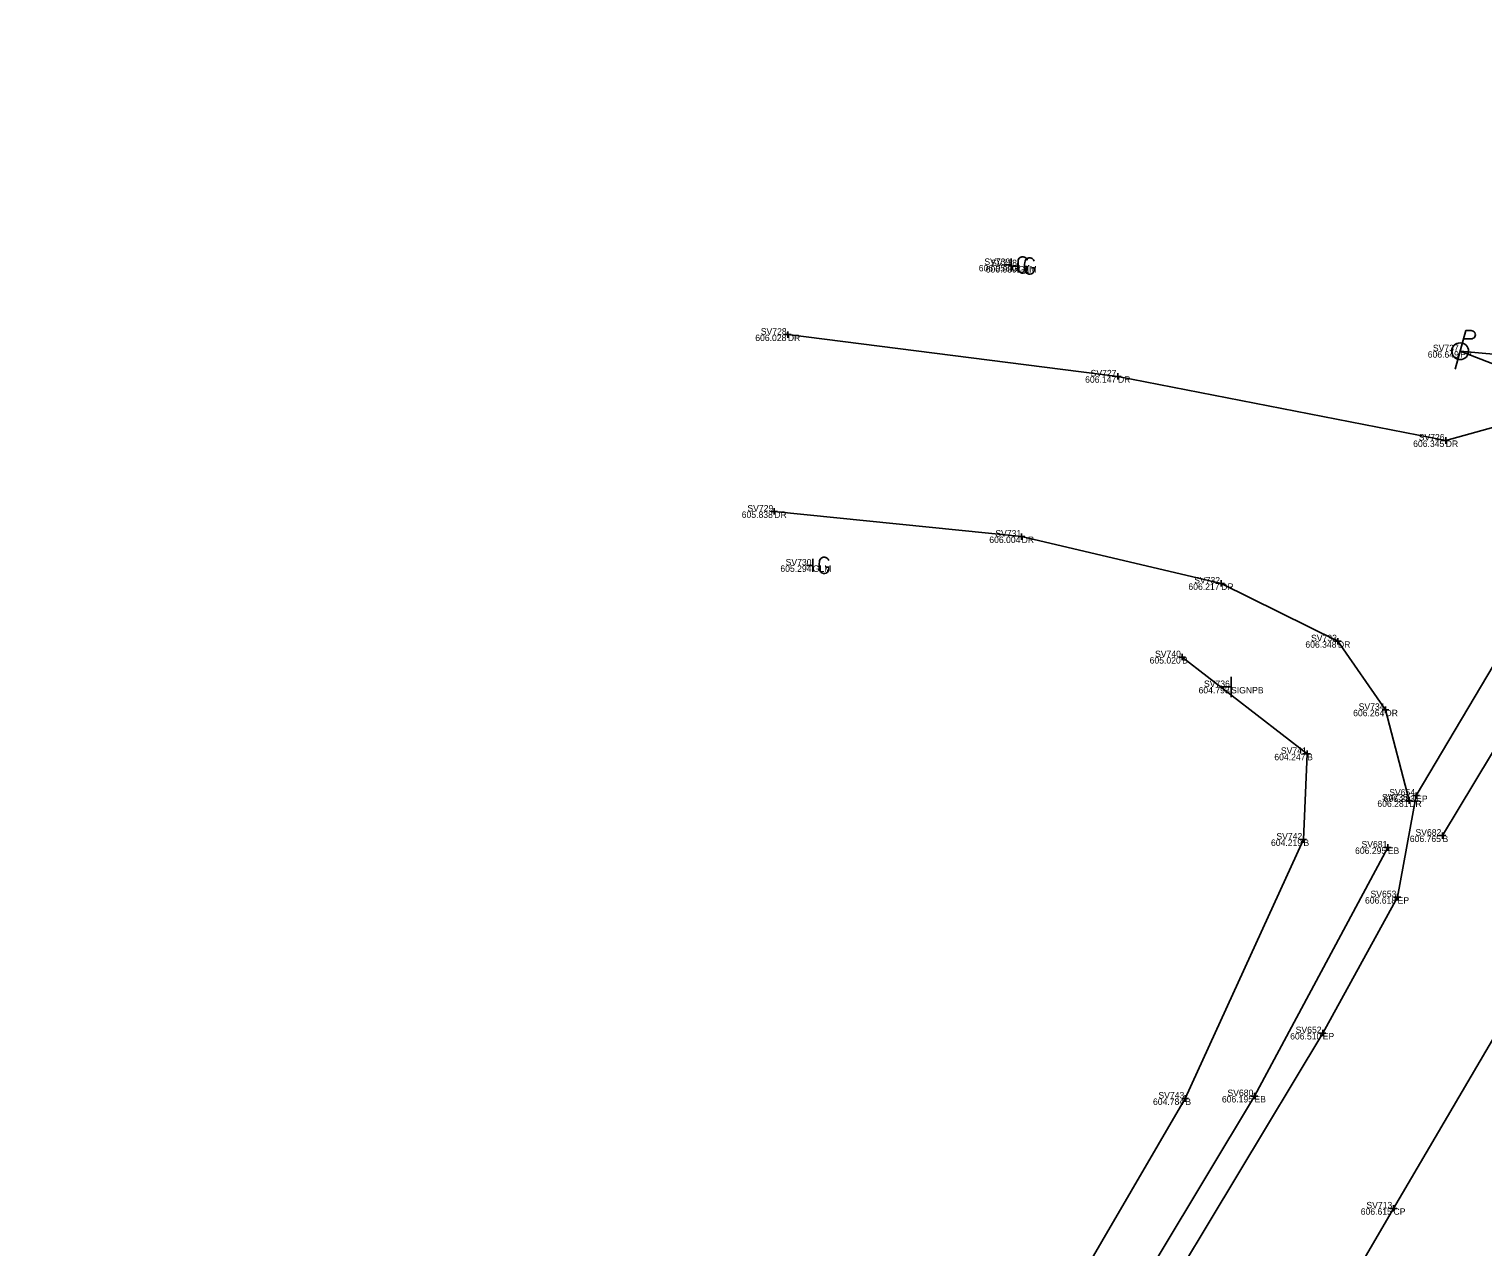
# Model space of a CAD drawing. Extents: x -2 to 1979875, y -2 to 232027.
# Drawn here: x 1978861.3 to 1978974.2, y 231930.6 to 232025.2 of the extents above; entities that cross this region are included whole.
import ezdxf

# ---------------------------------------------------------------- set-up
doc = ezdxf.new("R2010")
doc.units = 0
for name, color, linetype in [('_CIVIL_CONSTRUCTION', 7, 'Continuous'), ('GE_P_Alignment', 7, 'Continuous'), ('GE_X_Alignment', 7, 'Continuous'), ('GE_X_Alignment_1000_Curve_Data', 7, 'Continuous'), ('GE_X_Alignment_1000_Stations', 7, 'Continuous'), ('GE_X_Alignment_100_Curve_Data', 7, 'Continuous'), ('GE_X_Alignment_100_Stations', 7, 'Continuous'), ('GE_X_Alignment_500_Stations', 7, 'Continuous'), ('GE_X_CL', 7, 'Continuous'), ('SC_Scratch1', 7, 'Continuous'), ('UT_X_Electric_Cells', 7, 'Continuous'), ('UT_X_Gas_Cells', 7, 'Continuous'), ('UT_X_Overhead_Cable_TV', 7, 'Continuous'), ('UT_X_Overhead_Electric', 7, 'Continuous')]:
    doc.layers.add(name, color=color, linetype=linetype)

msp = doc.modelspace()

# ---------------------------------------------------------------- linework, layer by layer
at = {"layer": 'GE_P_Alignment'}
for points in [[(1978971.02, 231962.58), (1978982.35, 231981.4), (1978991.92, 231998.34)], [(1978950.81, 231976.44), (1978960.51, 231968.93), (1978960.22, 231962.28), (1978951.05, 231942.17), (1978940.37, 231923.86), (1978927.65, 231902.15), (1978916.58, 231882.84), (1978905.12, 231862.35), (1978893.68, 231842.71), (1978881.59, 231820.54), (1978870.08, 231799.88), (1978861.28, 231783.21)]]:
    msp.add_lwpolyline(points, dxfattribs=at)
at = {"layer": 'GE_X_Alignment_1000_Curve_Data'}
msp.add_lwpolyline([(1978877.19, 231774.62), (1978888.77, 231796.26), (1978900.69, 231818.02), (1978913.4, 231840.57), (1978929.2, 231868.19), (1978941.91, 231890.1), (1978954.45, 231911.73), (1978967.21, 231933.64), (1978980.41, 231956.12), (1978992.92, 231977.17), (1979005.51, 231998.49), (1979018.18, 232019.92)], dxfattribs=at)
at = {"layer": 'GE_X_Alignment_1000_Stations'}
msp.add_lwpolyline([(1978866.56, 231780.35), (1978878.04, 231801.75), (1978889.24, 231822.17), (1978900.83, 231842.54), (1978912.11, 231861.77), (1978922.51, 231879.69), (1978936.41, 231904.03), (1978948.54, 231925.3), (1978961.72, 231947.25), (1978967.53, 231957.8), (1978968.97, 231965.69), (1978979.03, 231982.65), (1978989.75, 231999.88), (1978994.31, 232003.86), (1979007.45, 232025.2)], dxfattribs=at)
at = {"layer": 'GE_X_Alignment_100_Curve_Data'}
for p, q in [((1978919.94, 232001.48), (1978920.44, 232001.48)), ((1978920.19, 232001.73), (1978920.19, 232001.23)), ((1978920.19, 232001.48), (1978920.19, 232001.48)), ((1978945.57, 231998.24), (1978946.07, 231998.24)), ((1978945.82, 231998.49), (1978945.82, 231997.99)), ((1978945.82, 231998.24), (1978945.82, 231998.24)), ((1978971.02, 231993.26), (1978971.52, 231993.26)), ((1978971.27, 231993.51), (1978971.27, 231993.01)), ((1978971.27, 231993.26), (1978971.27, 231993.26)), ((1978918.89, 231987.75), (1978919.39, 231987.75)), ((1978919.14, 231988), (1978919.14, 231987.5)), ((1978919.14, 231987.75), (1978919.14, 231987.75)), ((1978938.09, 231985.8), (1978938.59, 231985.8)), ((1978938.34, 231986.05), (1978938.34, 231985.55)), ((1978938.34, 231985.8), (1978938.34, 231985.8)), ((1978953.59, 231982.16), (1978954.09, 231982.16)), ((1978953.84, 231982.41), (1978953.84, 231981.91)), ((1978953.84, 231982.16), (1978953.84, 231982.16)), ((1978962.65, 231977.67), (1978963.15, 231977.67)), ((1978962.9, 231977.92), (1978962.9, 231977.42)), ((1978962.9, 231977.67), (1978962.9, 231977.67)), ((1978950.56, 231976.44), (1978951.06, 231976.44)), ((1978950.81, 231976.69), (1978950.81, 231976.19)), ((1978950.81, 231976.44), (1978950.81, 231976.44)), ((1978966.34, 231972.35), (1978966.84, 231972.35)), ((1978966.59, 231972.6), (1978966.59, 231972.1)), ((1978966.59, 231972.35), (1978966.59, 231972.35)), ((1978960.26, 231968.93), (1978960.76, 231968.93)), ((1978960.51, 231969.18), (1978960.51, 231968.68)), ((1978960.51, 231968.93), (1978960.51, 231968.93)), ((1978968.18, 231965.31), (1978968.68, 231965.31)), ((1978968.43, 231965.56), (1978968.43, 231965.06)), ((1978968.43, 231965.31), (1978968.43, 231965.31)), ((1978968.72, 231965.69), (1978969.22, 231965.69)), ((1978968.97, 231965.94), (1978968.97, 231965.44)), ((1978968.97, 231965.69), (1978968.97, 231965.69)), ((1978971.02, 231962.83), (1978971.02, 231962.33)), ((1978959.97, 231962.28), (1978960.47, 231962.28)), ((1978960.22, 231962.53), (1978960.22, 231962.03)), ((1978960.22, 231962.28), (1978960.22, 231962.28)), ((1978966.52, 231961.66), (1978967.02, 231961.66)), ((1978966.77, 231961.91), (1978966.77, 231961.41)), ((1978966.77, 231961.66), (1978966.77, 231961.66)), ((1978970.77, 231962.58), (1978971.27, 231962.58)), ((1978971.02, 231962.58), (1978971.02, 231962.58)), ((1978967.28, 231957.8), (1978967.78, 231957.8)), ((1978967.53, 231958.05), (1978967.53, 231957.55)), ((1978967.53, 231957.8), (1978967.53, 231957.8)), ((1978961.47, 231947.25), (1978961.97, 231947.25)), ((1978961.72, 231947.5), (1978961.72, 231947)), ((1978961.72, 231947.25), (1978961.72, 231947.25)), ((1978956.42, 231942.61), (1978956.42, 231942.11)), ((1978950.8, 231942.17), (1978951.3, 231942.17)), ((1978951.05, 231942.42), (1978951.05, 231941.92)), ((1978951.05, 231942.17), (1978951.05, 231942.17)), ((1978956.17, 231942.36), (1978956.67, 231942.36)), ((1978956.42, 231942.36), (1978956.42, 231942.36)), ((1978966.96, 231933.64), (1978967.46, 231933.64)), ((1978967.21, 231933.89), (1978967.21, 231933.39)), ((1978967.21, 231933.64), (1978967.21, 231933.64))]:
    msp.add_line(p, q, dxfattribs=at)
at = {"layer": 'GE_X_Alignment_500_Stations'}
for p, q in [((1978954.6, 231974.12), (1978953.8, 231974.12)), ((1978954.6, 231974.92), (1978954.6, 231973.32))]:
    msp.add_line(p, q, dxfattribs=at)
at = {"layer": 'GE_X_CL'}
for points in [[(1978988.03, 231999.45), (1978982, 231996.23), (1978971.27, 231993.26), (1978945.82, 231998.24), (1978920.19, 232001.48)], [(1978919.14, 231987.75), (1978938.34, 231985.8), (1978953.84, 231982.16), (1978962.9, 231977.67), (1978966.59, 231972.35), (1978968.43, 231965.31)]]:
    msp.add_lwpolyline(points, dxfattribs=at)
at = {"layer": 'SC_Scratch1'}
msp.add_lwpolyline([(1978864.95, 231781.2), (1978875.33, 231801.36), (1978886.66, 231822.09), (1978898.68, 231842.91), (1978910.29, 231862.88), (1978922.48, 231884.05), (1978933.85, 231904.31), (1978945.24, 231923.73), (1978956.42, 231942.36), (1978966.77, 231961.66)], dxfattribs=at)
at = {"layer": 'UT_X_Electric_Cells'}
for p, q in [((1978972.82, 232001.79), (1978972.01, 231998.79)), ((1978972.65, 232001.15), (1978973.24, 232001.15)), ((1978972.82, 232001.79), (1978973.24, 232001.79))]:
    msp.add_line(p, q, dxfattribs=at)
msp.add_circle((1978972.39, 232000.19), 0.65, dxfattribs=at)
msp.add_arc((1978973.25, 232001.47), 0.319, 268.8767, 91.1233, dxfattribs=at)
at = {"layer": 'UT_X_Gas_Cells'}
for p, q in [((1978937.54, 232006.89), (1978937.06, 232006.89)), ((1978937.54, 232006.39), (1978937.54, 232007.39)), ((1978938.07, 232006.8), (1978937.6, 232006.8)), ((1978938.07, 232006.3), (1978938.07, 232007.3)), ((1978922.12, 231983.56), (1978921.65, 231983.56)), ((1978922.12, 231983.06), (1978922.12, 231984.06))]:
    msp.add_line(p, q, dxfattribs=at)
for points in [[(1978938.78, 232007.27), (1978938.77, 232007.32), (1978938.74, 232007.37), (1978938.69, 232007.41), (1978938.62, 232007.47), (1978938.57, 232007.49), (1978938.53, 232007.5), (1978938.47, 232007.51), (1978938.35, 232007.51), (1978938.3, 232007.5), (1978938.28, 232007.49), (1978938.24, 232007.47), (1978938.16, 232007.41), (1978938.11, 232007.35), (1978938.08, 232007.27), (1978938.06, 232007.16), (1978938.04, 232007), (1978938.04, 232006.79), (1978938.05, 232006.63), (1978938.09, 232006.5), (1978938.15, 232006.38), (1978938.2, 232006.34), (1978938.26, 232006.3), (1978938.36, 232006.26), (1978938.47, 232006.26), (1978938.58, 232006.28), (1978938.62, 232006.3), (1978938.66, 232006.32), (1978938.7, 232006.36), (1978938.74, 232006.42), (1978938.78, 232006.51), (1978938.78, 232006.76), (1978938.57, 232006.76)], [(1978939.31, 232007.18), (1978939.3, 232007.23), (1978939.27, 232007.28), (1978939.22, 232007.33), (1978939.15, 232007.39), (1978939.11, 232007.41), (1978939.07, 232007.42), (1978939.01, 232007.43), (1978938.89, 232007.43), (1978938.84, 232007.42), (1978938.81, 232007.41), (1978938.77, 232007.39), (1978938.69, 232007.33), (1978938.64, 232007.26), (1978938.61, 232007.18), (1978938.59, 232007.07), (1978938.57, 232006.92), (1978938.57, 232006.71), (1978938.58, 232006.54), (1978938.62, 232006.41), (1978938.68, 232006.3), (1978938.73, 232006.26), (1978938.79, 232006.22), (1978938.9, 232006.18), (1978939.01, 232006.18), (1978939.12, 232006.2), (1978939.15, 232006.22), (1978939.19, 232006.24), (1978939.23, 232006.28), (1978939.27, 232006.33), (1978939.31, 232006.42), (1978939.31, 232006.67), (1978939.11, 232006.67)], [(1978923.36, 231983.94), (1978923.35, 231983.99), (1978923.32, 231984.04), (1978923.27, 231984.09), (1978923.2, 231984.15), (1978923.16, 231984.17), (1978923.12, 231984.18), (1978923.06, 231984.19), (1978922.94, 231984.19), (1978922.89, 231984.18), (1978922.86, 231984.17), (1978922.82, 231984.15), (1978922.74, 231984.09), (1978922.69, 231984.02), (1978922.66, 231983.94), (1978922.64, 231983.83), (1978922.62, 231983.68), (1978922.62, 231983.47), (1978922.63, 231983.3), (1978922.67, 231983.17), (1978922.73, 231983.06), (1978922.78, 231983.02), (1978922.84, 231982.98), (1978922.95, 231982.94), (1978923.06, 231982.94), (1978923.17, 231982.96), (1978923.2, 231982.98), (1978923.24, 231983), (1978923.28, 231983.04), (1978923.32, 231983.1), (1978923.36, 231983.18), (1978923.36, 231983.43), (1978923.16, 231983.43)]]:
    msp.add_lwpolyline(points, dxfattribs=at)
at = {"layer": 'UT_X_Overhead_Cable_TV'}
msp.add_line((1979041.07, 231994.22), (1978972.39, 232000.19), dxfattribs=at)
at = {"layer": 'UT_X_Overhead_Electric'}
msp.add_lwpolyline([(1978972.39, 232000.19), (1979025.8, 231979.51), (1978929, 231757.44), (1979009.41, 231399.95)], dxfattribs=at)

# ---------------------------------------------------------------- texts
at = {"layer": '_CIVIL_CONSTRUCTION'}
for s, p in [('606.058', (1978935.01, 232006.39)), ('606.089', (1978935.55, 232006.3)), ('606.028', (1978917.66, 232000.98)), ('606.649', (1978969.87, 231999.69)), ('606.147', (1978943.27, 231997.74)), ('606.345', (1978968.74, 231992.76)), ('605.838', (1978916.61, 231987.25)), ('606.004', (1978935.83, 231985.3)), ('605.294', (1978919.61, 231983.06)), ('606.217', (1978951.29, 231981.66)), ('606.348', (1978960.37, 231977.17)), ('605.020', (1978948.28, 231975.94)), ('604.793', (1978952.08, 231973.62)), ('606.264', (1978964.08, 231971.85)), ('604.247', (1978957.96, 231968.43)), ('606.281', (1978965.96, 231964.81)), ('606.283', (1978966.45, 231965.19)), ('604.219', (1978957.7, 231961.78)), ('606.295', (1978964.23, 231961.16)), ('606.765', (1978968.48, 231962.08)), ('606.618', (1978965, 231957.3)), ('606.510', (1978959.19, 231946.75)), ('604.784', (1978948.54, 231941.67)), ('606.195', (1978953.89, 231941.86)), ('606.615', (1978964.67, 231933.14))]:
    msp.add_text(s, height=0.5, dxfattribs=at).set_placement(p)
at = {"layer": 'GE_X_Alignment'}
for s, p in [('SV739', (1978935.45, 232006.89)), ('SV738', (1978935.97, 232006.8)), ('SV728', (1978918.09, 232001.48)), ('SV737', (1978970.27, 232000.19)), ('SV727', (1978943.7, 231998.24)), ('SV726', (1978969.17, 231993.26)), ('SV729', (1978917.05, 231987.75)), ('SV731', (1978936.3, 231985.8)), ('SV730', (1978920.02, 231983.56)), ('SV732', (1978951.74, 231982.16)), ('SV733', (1978960.81, 231977.67)), ('SV740', (1978948.7, 231976.44)), ('SV736', (1978952.5, 231974.12)), ('SV734', (1978964.51, 231972.35)), ('SV741', (1978958.47, 231968.93)), ('SV654', (1978966.88, 231965.69)), ('SV735', (1978966.32, 231965.31)), ('SV742', (1978958.12, 231962.28)), ('SV682', (1978968.92, 231962.58)), ('SV681', (1978964.73, 231961.66)), ('SV653', (1978965.43, 231957.8)), ('SV652', (1978959.62, 231947.25)), ('SV743', (1978948.96, 231942.17)), ('SV680', (1978954.32, 231942.36)), ('SV713', (1978965.11, 231933.64))]:
    msp.add_text(s, height=0.5, dxfattribs=at).set_placement(p)
at = {"layer": 'GE_X_Alignment_100_Stations'}
for s, p in [('GLM', (1978937.54, 232006.39)), ('GLM', (1978938.07, 232006.3)), ('DR', (1978920.19, 232000.98)), ('PP', (1978972.39, 231999.69)), ('DR', (1978945.82, 231997.74)), ('DR', (1978971.27, 231992.76)), ('DR', (1978919.14, 231987.25)), ('DR', (1978938.34, 231985.3)), ('GLM', (1978922.12, 231983.06)), ('DR', (1978953.84, 231981.66)), ('DR', (1978962.9, 231977.17)), ('B', (1978950.81, 231975.94)), ('SIGNPB', (1978954.6, 231973.62)), ('DR', (1978966.59, 231971.85)), ('B', (1978960.51, 231968.43)), ('DR', (1978968.43, 231964.81)), ('EP', (1978968.97, 231965.19)), ('B', (1978960.22, 231961.78)), ('EB', (1978966.77, 231961.16)), ('B', (1978971.02, 231962.08)), ('EP', (1978967.53, 231957.3)), ('EP', (1978961.72, 231946.75)), ('B', (1978951.05, 231941.67)), ('EB', (1978956.42, 231941.86)), ('CP', (1978967.21, 231933.14))]:
    msp.add_text(s, height=0.5, dxfattribs=at).set_placement(p)

doc.saveas('drawing.dxf')
